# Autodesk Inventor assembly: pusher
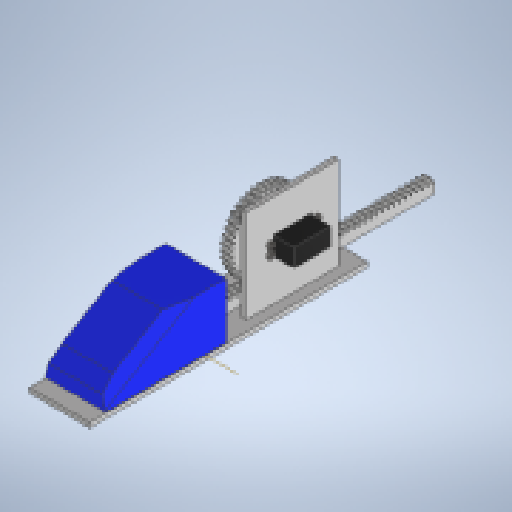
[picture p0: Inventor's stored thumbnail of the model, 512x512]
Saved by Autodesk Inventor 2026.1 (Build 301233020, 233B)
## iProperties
Created: 2026-10
Part Number: pusher
Document SubType Name: Assembly
Designer: alolo
Author: alolo
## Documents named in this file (9)
- C:\Users\hp\Documents\Inventor\DOM1_CartesianRobot\pusher.iam
- C:\Users\hp\Documents\Inventor\DOM1_CartesianRobot\pusher_pinion.ipt
- C:\Users\hp\Documents\Inventor\DOM1_CartesianRobot\Servo MG996R.ipt
- C:\Users\hp\Documents\Inventor\DOM1_CartesianRobot\pusher_rack.ipt
- C:\Users\hp\Documents\Inventor\DOM1_CartesianRobot\pusher_base.ipt
- C:\Users\hp\Documents\Inventor\DOM1_CartesianRobot\pusher_support.ipt
- C:\Users\hp\Documents\Inventor\DOM1_CartesianRobot\pusher_punch.ipt
- C:\Users\hp\Documents\Inventor\Content Center Files\R2026\en-US\ISO 4017(1)\ISO 4017 - M4 x 12 - ISO.ipt
- C:\Users\hp\Documents\Inventor\Content Center Files\R2026\en-US\ISO 4032(2)\ISO 4032 - M4 - ISO.ipt
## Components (14 placed, 8 different names)
1. Servo MG996R:1
2. pusher_base:1 — Mate:1, Mate:2, Mate:11, Slider:2, Flush:2, Mate:14
3. pusher_support
4. pusher_pinion:1 — Rotational:1, Rotation/Translation:1, Flush:1
5. pusher_rack:1 — Slider:2, Rotation/Translation:1, Mate:12, Mate:13, Flush:1
6. pusher_punch:2 — Mate:12, Mate:13, Mate:14
7. ISO 4017 M4 x 12:1 — Mate:15, Mate:16
8. ISO 4032 M4:1 — Mate:23, Mate:24
9. ISO 4017 M4 x 12:2 — Mate:17, Mate:18
10. ISO 4017 M4 x 12:3 — Mate:19, Mate:20
11. ISO 4017 M4 x 12:4 — Mate:21, Mate:22
12. ISO 4032 M4:2 — Mate:25, Mate:26
13. ISO 4032 M4:3 — Mate:27, Mate:28
14. ISO 4032 M4:4 — Mate:29, Mate:30
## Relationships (27: Mate 22, Flush 2, RevoluteJoint 1, TranslationJoint 1, RelateRotateTranslate 1)
- Mate:1: pusher_base:1
- Mate:2: pusher_base:1
- Rotational:1 [RevoluteJoint]: pusher_pinion:1
- Mate:11: pusher_base:1
- Slider:2 [TranslationJoint]: pusher_base:1 ↔ pusher_rack:1
- Rotation/Translation:1 [RelateRotateTranslate]: pusher_pinion:1 ↔ pusher_rack:1
- Mate:12: pusher_rack:1 ↔ pusher_punch:2
- Mate:13: pusher_rack:1 ↔ pusher_punch:2
- Flush:1: pusher_pinion:1 ↔ pusher_rack:1
- Flush:2: pusher_base:1
- Mate:14: pusher_base:1 ↔ pusher_punch:2
- Mate:15: ISO 4017 M4 x 12:1
- Mate:16: ISO 4017 M4 x 12:1
- Mate:17: ISO 4017 M4 x 12:2
- Mate:18: ISO 4017 M4 x 12:2
- Mate:19: ISO 4017 M4 x 12:3
- Mate:20: ISO 4017 M4 x 12:3
- Mate:21: ISO 4017 M4 x 12:4
- Mate:22: ISO 4017 M4 x 12:4
- Mate:23: ISO 4032 M4:1
- Mate:24: ISO 4032 M4:1
- Mate:25: ISO 4032 M4:2
- Mate:26: ISO 4032 M4:2
- Mate:27: ISO 4032 M4:3
- Mate:28: ISO 4032 M4:3
- Mate:29: ISO 4032 M4:4
- Mate:30: ISO 4032 M4:4
